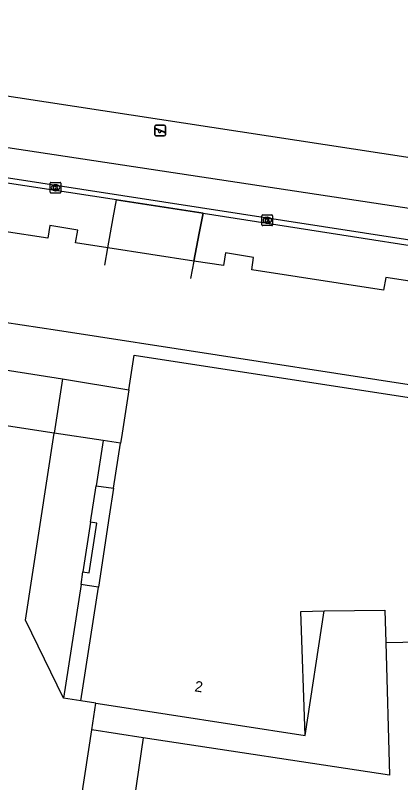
# Model space of a CAD drawing. Extents: x 161094 to 161705, y 379509 to 380907.
# Drawn here: x 161386.9 to 161423.1, y 380181.5 to 380253.5 of the extents above; entities that cross this region are included whole.
import ezdxf

# ---------------------------------------------------------------- set-up
doc = ezdxf.new("R2010")
doc.units = 0
for name, color, linetype in [('IMGEO_Groenvoorziening', 7, 'Continuous'), ('IMGEO_Hek', 7, 'Continuous'), ('IMGEO_Kolk', 7, 'Continuous'), ('IMGEO_Pand', 7, 'Continuous'), ('IMGEO_Pand_nummerreeks', 7, 'Continuous'), ('IMGEO_Parkeervlak_gesloten', 7, 'Continuous'), ('IMGEO_Parkeervlak_open', 7, 'Continuous'), ('IMGEO_Speelvoorziening', 7, 'Continuous'), ('IMGEO_Terreindeel_open', 7, 'Continuous'), ('IMGEO_Voetpad_gesloten', 7, 'Continuous'), ('IMGEO_Voetpad_open', 7, 'Continuous')]:
    doc.layers.add(name, color=color, linetype=linetype)

msp = doc.modelspace()

# ---------------------------------------------------------------- linework, layer by layer
at = {"layer": 'IMGEO_Groenvoorziening'}
for points in [[(161435.81, 380217.001), (161390.875, 380223.949), (161375.926, 380226.19)], [(161391.337, 380219.395), (161397.566, 380218.371)], [(161396.792, 380213.349), (161395.158, 380213.601)]]:
    msp.add_lwpolyline(points, dxfattribs=at)
at = {"layer": 'IMGEO_Hek'}
for points in [[(161396.413, 380236.189), (161361.584, 380241.511)], [(161395.611, 380231.692), (161396.111, 380234.498), (161396.413, 380236.189)], [(161404.532, 380234.95), (161396.413, 380236.189)], [(161404.532, 380234.95), (161404.176, 380233.084), (161403.674, 380230.45)], [(161404.532, 380234.95), (161438.956, 380229.56)], [(161395.319, 380230.053), (161395.611, 380231.692)], [(161403.674, 380230.45), (161403.361, 380228.811)]]:
    msp.add_lwpolyline(points, dxfattribs=at)
at = {"layer": 'IMGEO_Kolk'}
for p, q in [((161390.187, 380236.916), (161390.187, 380237.768)), ((161390.262, 380237.842), (161391.114, 380237.842)), ((161391.188, 380237.768), (161391.188, 380236.916)), ((161390.698, 380237.062), (161390.673, 380237.062)), ((161390.675, 380237.622), (161390.7, 380237.622)), ((161391.114, 380236.842), (161390.262, 380236.842)), ((161410.053, 380233.859), (161410.053, 380234.711)), ((161410.128, 380234.785), (161410.98, 380234.785)), ((161410.541, 380234.565), (161410.566, 380234.565)), ((161411.054, 380234.711), (161411.054, 380233.859)), ((161410.98, 380233.785), (161410.128, 380233.785)), ((161410.564, 380234.005), (161410.539, 380234.005))]:
    msp.add_line(p, q, dxfattribs=at)
for points in [[(161390.187, 380236.916), (161390.187, 380237.768)], [(161390.262, 380237.842), (161391.114, 380237.842)], [(161391.188, 380237.768), (161391.188, 380236.916)], [(161390.508, 380237.542), (161390.631, 380237.542), (161390.631, 380237.391), (161390.761, 380237.542), (161390.925, 380237.542), (161390.779, 380237.391), (161390.932, 380237.142), (161390.78, 380237.142), (161390.695, 380237.306), (161390.631, 380237.239), (161390.631, 380237.142), (161390.508, 380237.142), (161390.508, 380237.542)], [(161391.114, 380236.842), (161390.262, 380236.842)], [(161410.053, 380233.859), (161410.053, 380234.711)], [(161410.128, 380234.785), (161410.98, 380234.785)], [(161410.374, 380234.485), (161410.497, 380234.485), (161410.497, 380234.334), (161410.627, 380234.485), (161410.791, 380234.485), (161410.645, 380234.334), (161410.798, 380234.085), (161410.646, 380234.085), (161410.561, 380234.249), (161410.497, 380234.182), (161410.497, 380234.085), (161410.374, 380234.085), (161410.374, 380234.485)], [(161411.054, 380234.711), (161411.054, 380233.859)], [(161410.98, 380233.785), (161410.128, 380233.785)]]:
    msp.add_lwpolyline(points, dxfattribs=at)
for centre, start, end in [((161390.264, 380237.766), 91.55205, 178.44795), ((161390.264, 380237.766), 91.55205, 178.44795), ((161391.112, 380237.766), 1.55205, 88.44795), ((161391.112, 380237.766), 1.55205, 88.44795), ((161390.264, 380236.918), 181.55205, 268.44795), ((161390.264, 380236.918), 181.55205, 268.44795), ((161391.112, 380236.918), 271.55205, 358.44795), ((161391.112, 380236.918), 271.55205, 358.44795), ((161410.13, 380234.709), 91.55205, 178.44795), ((161410.13, 380234.709), 91.55205, 178.44795), ((161410.978, 380234.709), 1.55205, 88.44795), ((161410.978, 380234.709), 1.55205, 88.44795), ((161410.13, 380233.861), 181.55205, 268.44795), ((161410.13, 380233.861), 181.55205, 268.44795), ((161410.978, 380233.861), 271.55205, 358.44795), ((161410.978, 380233.861), 271.55205, 358.44795)]:
    msp.add_arc(centre, 0.0765, start, end, dxfattribs=at)
for centre, major_axis, ratio, start_param, end_param in [((161390.674, 380237.342), (-0.387, 0.002), 0.722429, 4.712389, 7.853982), ((161390.699, 380237.342), (-0.39, 0.002), 0.717154, 1.570796, 4.712389), ((161410.54, 380234.285), (-0.387, 0.002), 0.722429, 4.712389, 7.853982), ((161410.565, 380234.285), (-0.39, 0.002), 0.717154, 1.570796, 4.712389)]:
    msp.add_ellipse(centre, major_axis=major_axis, ratio=ratio, start_param=start_param, end_param=end_param, dxfattribs=at)
at = {"layer": 'IMGEO_Pand'}
for points in [[(161397.566, 380218.371), (161398.066, 380221.612), (161430.36, 380216.65), (161430.062, 380214.725)], [(161397.566, 380218.371), (161396.873, 380213.882), (161396.792, 380213.349)], [(161396.139, 380209.118), (161396.792, 380213.349)], [(161396.139, 380209.118), (161395.734, 380206.496), (161394.708, 380199.845)], [(161421.663, 380194.634), (161434.402, 380194.895), (161434.264, 380202.041)], [(161393.061, 380189.161), (161394.708, 380199.845)], [(161414.092, 380185.905), (161413.711, 380197.559), (161415.884, 380197.601)], [(161415.884, 380197.601), (161421.589, 380197.688), (161421.663, 380194.634)], [(161394.485, 380188.941), (161393.061, 380189.161)], [(161394.485, 380188.941), (161394.698, 380188.908), (161414.092, 380185.905)]]:
    msp.add_lwpolyline(points, dxfattribs=at)
at = {"layer": 'IMGEO_Parkeervlak_gesloten'}
for points in [[(161390.561, 380214.301), (161375.644, 380216.573)], [(161391.442, 380189.428), (161387.886, 380196.742), (161390.561, 380214.301)], [(161393.061, 380189.161), (161391.442, 380189.428)], [(161392.782, 380177.842), (161394.1, 380186.433)]]:
    msp.add_lwpolyline(points, dxfattribs=at)
at = {"layer": 'IMGEO_Parkeervlak_open'}
for points in [[(161375.644, 380216.573), (161376.403, 380221.743), (161391.337, 380219.395)], [(161391.337, 380219.395), (161390.561, 380214.301)], [(161395.158, 380213.601), (161390.561, 380214.301)], [(161395.158, 380213.601), (161394.505, 380209.351)], [(161393.978, 380205.925), (161393.264, 380201.278)], [(161393.082, 380200.096), (161391.442, 380189.428)], [(161398.904, 380185.676), (161397.648, 380177.109), (161392.782, 380177.842)]]:
    msp.add_lwpolyline(points, dxfattribs=at)
at = {"layer": 'IMGEO_Speelvoorziening'}
for p, q in [((161400.002, 380242.299), (161400.002, 380243.099)), ((161400.002, 380243.099), (161400.002, 380242.299)), ((161400.385, 380242.727), (161400.046, 380242.864)), ((161400.071, 380242.924), (161400.947, 380242.571)), ((161400.102, 380243.199), (161400.892, 380243.199)), ((161400.892, 380243.199), (161400.102, 380243.199)), ((161400.992, 380243.099), (161400.992, 380242.299)), ((161400.992, 380242.299), (161400.992, 380243.099)), ((161400.892, 380242.199), (161400.102, 380242.199)), ((161400.102, 380242.199), (161400.892, 380242.199)), ((161400.923, 380242.511), (161400.583, 380242.648))]:
    msp.add_line(p, q, dxfattribs=at)
for centre, radius, start, end in [((161400.102, 380243.099), 0.1, 90, 180), ((161400.102, 380243.099), 0.1, 90, 180), ((161400.059, 380242.894), 0.0327, 68.07798, 248.07798), ((161400.892, 380243.099), 0.1, 0, 90), ((161400.892, 380243.099), 0.1, 360, 90), ((161400.102, 380242.299), 0.1, 180, 270), ((161400.102, 380242.299), 0.1, 180, 270), ((161400.464, 380242.637), 0.12, 130.99278, 5.16318), ((161400.892, 380242.299), 0.1, 270, 0), ((161400.892, 380242.299), 0.1, 270, 0), ((161400.935, 380242.541), 0.0327, 248.07798, 68.07798)]:
    msp.add_arc(centre, radius, start, end, dxfattribs=at)
at = {"layer": 'IMGEO_Terreindeel_open'}
msp.add_lwpolyline([(161449.975, 380341.416), (161384, 380351.548), (161368.719, 380250), (161368.518, 380248.665), (161434.571, 380238.556), (161436.285, 380250), (161449.975, 380341.416)], dxfattribs=at)
at = {"layer": 'IMGEO_Voetpad_gesloten'}
for points in [[(161396.413, 380236.189), (161361.584, 380241.511)], [(161395.611, 380231.692), (161392.575, 380232.159), (161392.771, 380233.346), (161390.164, 380233.785), (161389.956, 380232.608), (161377.647, 380234.485), (161377.818, 380235.694), (161375.151, 380236.109), (161374.962, 380234.946), (161360.618, 380237.083), (161360.488, 380235.811)], [(161395.611, 380231.692), (161396.111, 380234.498), (161396.413, 380236.189)], [(161396.413, 380236.189), (161404.532, 380234.95)], [(161403.674, 380230.45), (161404.176, 380233.084), (161404.532, 380234.95)], [(161404.532, 380234.95), (161438.956, 380229.56)], [(161403.674, 380230.45), (161395.611, 380231.692)], [(161438.468, 380223.685), (161438.694, 380225.03), (161424.183, 380227.314), (161424.327, 380228.488), (161421.675, 380228.899), (161421.452, 380227.736), (161409.109, 380229.629), (161409.258, 380230.799), (161406.633, 380231.213), (161406.436, 380230.025), (161403.674, 380230.45)]]:
    msp.add_lwpolyline(points, dxfattribs=at)
at = {"layer": 'IMGEO_Voetpad_open'}
for points in [[(161362.621, 380244.695), (161362.493, 380243.855), (161362.232, 380241.926), (161366.609, 380241.3), (161438.493, 380230.189), (161441.451, 380250), (161456.089, 380348.027), (161381.017, 380359.406), (161380.127, 380359.542), (161379.665, 380356.51)], [(161362.621, 380244.695), (161437.723, 380233.337), (161454.471, 380345.13), (161379.665, 380356.51)], [(161393.978, 380205.925), (161394.505, 380209.351)], [(161394.505, 380209.351), (161396.139, 380209.118)], [(161393.264, 380201.278), (161393.854, 380201.191), (161394.571, 380205.841), (161393.978, 380205.925)], [(161393.082, 380200.096), (161393.264, 380201.278)], [(161394.708, 380199.845), (161393.671, 380200.005), (161393.082, 380200.096)], [(161414.092, 380185.905), (161415.884, 380197.601)], [(161421.663, 380194.634), (161422.025, 380182.174), (161398.904, 380185.676)], [(161394.1, 380186.433), (161394.485, 380188.941)], [(161398.904, 380185.676), (161394.1, 380186.433)]]:
    msp.add_lwpolyline(points, dxfattribs=at)

# ---------------------------------------------------------------- texts
at = {"layer": 'IMGEO_Pand_nummerreeks'}
msp.add_text('2', height=1, rotation=351.19937, dxfattribs=at).set_placement((161403.687, 380190.066))

doc.saveas('drawing.dxf')
